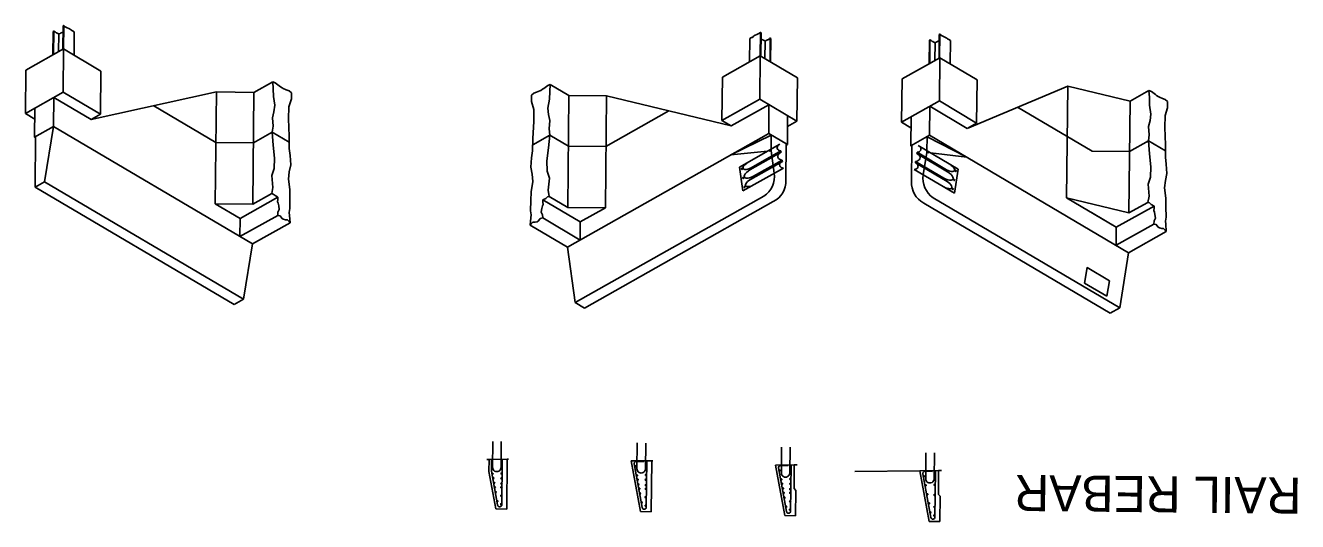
# Model space of a CAD drawing. Extents: x 631918 to 632319, y 373181 to 373282.
# Drawn here: x 631918.3 to 632006.4, y 373247.3 to 373281.7 of the extents above; entities that cross this region are included whole.
import ezdxf

# ---------------------------------------------------------------- set-up
doc = ezdxf.new("R2010")
doc.units = 0
for name, color, linetype in [('B_Boring', 7, 'Continuous'), ('BD-PROP-COSS', 7, 'Continuous'), ('BD-REMOVE', 7, 'Continuous'), ('R_Border_Scale', 7, 'Continuous'), ('R_Proposed Const Limits Cut', 7, 'Continuous'), ('R_Road Edge of Travel', 7, 'Continuous'), ('R_Shade Removal', 7, 'Continuous')]:
    doc.layers.add(name, color=color, linetype=linetype)

msp = doc.modelspace()

# ---------------------------------------------------------------- linework, layer by layer
at = {"layer": 'B_Boring'}
for p, q in [((631969.792, 373272.95), (631969.934, 373272.964)), ((631969.934, 373272.964), (631969.935, 373273.03)), ((631970.151, 373271.419), (631969.934, 373272.964)), ((631980.469, 373271.316), (631980.716, 373272.857)), ((631980.716, 373272.857), (631980.717, 373272.922)), ((631980.858, 373272.84), (631980.716, 373272.857))]:
    msp.add_line(p, q, dxfattribs=at)
at = {"layer": 'BD-PROP-COSS'}
for p, q in [((631950.664, 373252.836), (631950.646, 373251.044)), ((631951.247, 373252.83), (631951.229, 373251.038)), ((631960.663, 373252.736), (631960.645, 373250.945)), ((631961.247, 373252.73), (631961.229, 373250.939)), ((631970.661, 373252.454), (631970.643, 373250.663)), ((631971.244, 373252.449), (631971.226, 373250.657)), ((631980.657, 373252.052), (631980.64, 373250.261)), ((631981.241, 373252.047), (631981.223, 373250.255)), ((631950.56, 373250.791), (631950.568, 373251.599)), ((631951.287, 373248.474), (631951.318, 373251.591)), ((631960.452, 373251.286), (631960.996, 373248.267)), ((631961.121, 373251.452), (631960.597, 373251.457)), ((631961.286, 373248.292), (631961.318, 373251.492)), ((631971.119, 373251.171), (631970.595, 373251.176)), ((631971.283, 373248.01), (631971.315, 373251.21)), ((631950.56, 373250.791), (631950.982, 373248.447)), ((631970.45, 373251.004), (631970.994, 373247.985)), ((631980.447, 373250.602), (631980.991, 373247.583)), ((631981.115, 373250.768), (631980.592, 373250.774)), ((631981.28, 373247.608), (631981.312, 373250.808))]:
    msp.add_line(p, q, dxfattribs=at)
for centre in [(631950.606, 373251.211), (631951.274, 373251.329), (631960.528, 373251.112), (631961.273, 373251.23), (631950.641, 373250.586), (631950.693, 373250.293), (631951.263, 373250.288), (631951.267, 373250.621), (631960.64, 373250.486), (631960.693, 373250.194), (631961.263, 373250.188), (631961.266, 373250.522), (631970.525, 373250.831), (631970.638, 373250.205), (631971.264, 373250.24), (631971.271, 373250.948), (631980.522, 373250.429), (631981.267, 373250.546), (631950.753, 373249.96), (631950.806, 373249.667), (631950.865, 373249.333), (631951.257, 373249.663), (631951.26, 373249.913), (631960.753, 373249.86), (631960.805, 373249.568), (631961.257, 373249.563), (631961.259, 373249.813), (631970.69, 373249.912), (631970.75, 373249.578), (631971.257, 373249.532), (631971.261, 373249.907), (631980.634, 373249.802), (631981.26, 373249.838), (631950.978, 373248.707), (631951.246, 373248.496), (631951.251, 373249.08), (631960.865, 373249.234), (631960.977, 373248.608), (631961.251, 373248.98), (631970.803, 373249.286), (631970.863, 373248.952), (631971.249, 373248.698), (631971.254, 373249.282), (631980.747, 373249.176), (631980.859, 373248.55), (631981.253, 373249.13), (631961.245, 373248.397), (631970.975, 373248.326), (631971.243, 373248.115), (631980.972, 373247.924), (631981.239, 373247.713), (631981.245, 373248.296)]:
    msp.add_circle(centre, 0.0417, dxfattribs=at)
for centre, radius, start, end in [((631960.596, 373251.312), 0.146, 89.43036, 190.21458), ((631970.594, 373251.03), 0.146, 89.43036, 190.21458), ((631950.938, 373251.041), 0.292, 179.43036, 359.43036), ((631960.937, 373250.942), 0.292, 179.43036, 359.43036), ((631970.935, 373250.66), 0.292, 179.43036, 359.43036), ((631980.59, 373250.628), 0.146, 89.43036, 190.21458), ((631980.931, 373250.258), 0.292, 179.43036, 359.43036), ((631961.14, 373248.293), 0.146, 190.21458, 359.43036), ((631971.138, 373248.011), 0.146, 190.21458, 359.43036), ((631981.134, 373247.609), 0.146, 190.21458, 359.43036)]:
    msp.add_arc(centre, radius, start, end, dxfattribs=at)
msp.add_ellipse((631951.134, 373248.476), major_axis=(-0.002, -0.161), ratio=0.951273, start_param=4.900609, end_param=7.853982, dxfattribs=at)
at = {"layer": 'R_Border_Scale'}
for p, q in [((631931.485, 373273.544), (631927.18, 373276.087)), ((631992.156, 373272.941), (631986.99, 373275.992)), ((631958.498, 373273.275), (631962.853, 373275.732)), ((631934.083, 373273.518), (631935.39, 373274.255)), ((631936.563, 373273.562), (631935.39, 373274.255)), ((631953.422, 373273.395), (631954.608, 373274.064)), ((631955.9, 373273.301), (631954.608, 373274.064)), ((631931.485, 373273.544), (631934.083, 373273.518)), ((631958.498, 373273.275), (631955.9, 373273.301)), ((631994.754, 373272.915), (631996.061, 373273.652)), ((631997.234, 373272.959), (631996.061, 373273.652)), ((631992.156, 373272.941), (631994.754, 373272.915)), ((631950.403, 373251.591), (631951.664, 373251.604)), ((631960.246, 373251.49), (631961.663, 373251.504)), ((631970.244, 373251.209), (631971.536, 373251.222)), ((631980.24, 373250.806), (631981.532, 373250.819))]:
    msp.add_line(p, q, dxfattribs=at)
at = {"layer": 'R_Proposed Const Limits Cut'}
for p, q in [((631967.742, 373271.841), (631970.547, 373273.424)), ((631982.886, 373271.69), (631980.112, 373273.329)), ((631968.467, 373271.649), (631970.626, 373272.867)), ((631968.499, 373270.988), (631970.714, 373272.237)), ((631968.547, 373271.794), (631970.613, 373272.96)), ((631968.715, 373271.21), (631970.701, 373272.33)), ((631970.626, 373272.867), (631970.613, 373272.96)), ((631970.714, 373272.237), (631970.701, 373272.33)), ((631979.922, 373272.146), (631979.937, 373272.238)), ((631981.9, 373271.079), (631979.937, 373272.238)), ((631980.023, 373272.773), (631980.038, 373272.866)), ((631982.156, 373271.513), (631980.023, 373272.773)), ((631982.08, 373271.66), (631980.038, 373272.866)), ((631967.974, 373270.19), (631967.742, 373271.841)), ((631967.974, 373270.19), (631970.779, 373271.773)), ((631982.621, 373270.045), (631979.848, 373271.683)), ((631982.112, 373270.852), (631979.922, 373272.146)), ((631982.621, 373270.045), (631982.886, 373271.69)), ((631991.644, 373263.811), (631991.816, 373264.88)), ((631993.187, 373262.899), (631993.359, 373263.969))]:
    msp.add_line(p, q, dxfattribs=at)
for points in [[(631993.359, 373263.969), (631991.816, 373264.88), (631991.816, 373264.88), (631993.359, 373263.969)], [(631993.187, 373262.899), (631991.644, 373263.811), (631991.644, 373263.811), (631993.187, 373262.899)]]:
    msp.add_lwpolyline(points, close=True, dxfattribs=at)
for centre, major_axis, ratio, start_param, end_param in [((631970.616, 373273.188), (0.267, -0.005), 0.854896, 2.174054, 4.712811), ((631980.038, 373273.094), (0.267, -0.001), 0.854896, 4.711967, 7.250724), ((631970.705, 373272.594), (0.309, -0.005), 0.854896, 2.174054, 4.712811), ((631979.938, 373272.503), (0.309, -0.001), 0.854896, 4.711967, 7.250724), ((631968.44, 373271.984), (-0.44, -0.248), 0.432148, 4.712389, 7.853982), ((631968.591, 373271.43), (-0.508, -0.287), 0.432148, 4.712389, 7.853982), ((631970.783, 373272.002), (0.267, -0.005), 0.854896, 2.174054, 4.712811), ((631979.848, 373271.911), (0.267, -0.001), 0.854896, 4.711967, 7.250724), ((631982.028, 373271.296), (0.502, -0.297), 0.432148, 4.712389, 7.853982), ((631982.191, 373271.847), (0.435, -0.257), 0.432148, 4.712389, 7.853982), ((631968.606, 373270.798), (-0.44, -0.248), 0.432148, 4.712389, 7.853982), ((631982.001, 373270.664), (0.435, -0.257), 0.432148, 4.712389, 7.853982)]:
    msp.add_ellipse(centre, major_axis=major_axis, ratio=ratio, start_param=start_param, end_param=end_param, dxfattribs=at)
for centre, major_axis in [((631967.915, 373271.727), (-0.0216, -0.0437)), ((631968.539, 373271.74), (-0.0216, -0.0437)), ((631982.086, 373271.605), (0.0207, -0.0441)), ((631982.711, 373271.58), (0.0207, -0.0441)), ((631968.003, 373271.098), (-0.0216, -0.0437)), ((631968.091, 373270.468), (-0.0216, -0.0437)), ((631968.628, 373271.11), (-0.0216, -0.0437)), ((631981.985, 373270.978), (0.0207, -0.0441)), ((631982.61, 373270.952), (0.0207, -0.0441)), ((631982.509, 373270.325), (0.0207, -0.0441))]:
    msp.add_ellipse(centre, major_axis=major_axis, ratio=0.68171, dxfattribs=at)
at = {"layer": 'R_Road Edge of Travel'}
for p, q in [((631920.205, 373279.609), (631920.221, 373281.244)), ((631920.246, 373279.632), (631920.262, 373281.267)), ((631920.598, 373279.831), (631920.61, 373281.062)), ((631920.89, 373279.996), (631920.906, 373281.631)), ((631920.931, 373280.019), (631920.947, 373281.654)), ((631921.667, 373279.595), (631921.683, 373281.219)), ((631969.179, 373279.539), (631969.195, 373281.174)), ((631969.219, 373279.515), (631969.236, 373281.15)), ((631981.602, 373279.416), (631981.618, 373281.051)), ((631968.435, 373279.13), (631968.451, 373280.754)), ((631969.508, 373279.345), (631969.52, 373280.575)), ((631969.856, 373279.139), (631969.872, 373280.774)), ((631969.897, 373279.115), (631969.913, 373280.75)), ((631980.876, 373279.006), (631980.892, 373280.641)), ((631980.917, 373279.029), (631980.933, 373280.664)), ((631981.269, 373279.228), (631981.281, 373280.459)), ((631981.561, 373279.392), (631981.577, 373281.028)), ((631982.338, 373278.992), (631982.354, 373280.616))]:
    msp.add_line(p, q, dxfattribs=at)
for points in [[(631920.221, 373281.244), (631920.262, 373281.267), (631920.308, 373281.242), (631920.346, 373281.206), (631920.421, 373281.15), (631920.457, 373281.136), (631920.537, 373281.104), (631920.61, 373281.062), (631920.691, 373281.09), (631920.736, 373281.115), (631920.839, 373281.166), (631920.868, 373281.17), (631920.902, 373281.19)], [(631920.906, 373281.631), (631920.947, 373281.654), (631921.059, 373281.562), (631921.148, 373281.517), (631921.348, 373281.429), (631921.423, 373281.37), (631921.48, 373281.32), (631921.511, 373281.296), (631921.566, 373281.275), (631921.683, 373281.219)], [(631969.236, 373281.15), (631969.195, 373281.174), (631969.081, 373281.085), (631968.992, 373281.041), (631968.79, 373280.957), (631968.714, 373280.9), (631968.656, 373280.851), (631968.624, 373280.828), (631968.569, 373280.808), (631968.451, 373280.754)], [(631981.577, 373281.028), (631981.618, 373281.051), (631981.73, 373280.959), (631981.819, 373280.914), (631982.019, 373280.825), (631982.094, 373280.767), (631982.151, 373280.717), (631982.182, 373280.693), (631982.237, 373280.672), (631982.354, 373280.616)], [(631969.913, 373280.75), (631969.872, 373280.774), (631969.827, 373280.749), (631969.787, 373280.714), (631969.711, 373280.659), (631969.675, 373280.646), (631969.594, 373280.616), (631969.52, 373280.575), (631969.44, 373280.605), (631969.396, 373280.631), (631969.293, 373280.685), (631969.265, 373280.689), (631969.231, 373280.709)], [(631980.892, 373280.641), (631980.933, 373280.664), (631980.978, 373280.638), (631981.017, 373280.602), (631981.092, 373280.546), (631981.128, 373280.533), (631981.208, 373280.5), (631981.281, 373280.459), (631981.362, 373280.487), (631981.407, 373280.512), (631981.51, 373280.563), (631981.539, 373280.567), (631981.573, 373280.586)]]:
    msp.add_lwpolyline(points, dxfattribs=at)
at = {"layer": 'R_Shade Removal'}
for p, q in [((631918.328, 373278.55), (631920.941, 373280.024)), ((631920.911, 373277.024), (631920.941, 373280.024)), ((631923.524, 373278.498), (631920.941, 373280.024)), ((631966.557, 373278.071), (631969.169, 373279.545)), ((631969.14, 373276.545), (631969.169, 373279.545)), ((631971.753, 373278.019), (631969.169, 373279.545)), ((631978.999, 373277.947), (631981.612, 373279.421)), ((631981.582, 373276.421), (631981.612, 373279.421)), ((631984.195, 373277.895), (631981.612, 373279.421)), ((631918.298, 373275.55), (631918.328, 373278.55)), ((631923.494, 373275.499), (631923.524, 373278.498)), ((631934.118, 373277.018), (631935.425, 373277.755)), ((631955.935, 373276.801), (631954.643, 373277.564)), ((631966.527, 373275.071), (631966.557, 373278.071)), ((631971.723, 373275.019), (631971.753, 373278.019)), ((631978.969, 373274.947), (631978.999, 373277.947)), ((631984.165, 373274.895), (631984.195, 373277.895)), ((631918.298, 373275.55), (631920.911, 373277.024)), ((631920.238, 373274.656), (631920.258, 373276.656)), ((631922.841, 373275.13), (631920.258, 373276.656)), ((631923.494, 373275.499), (631920.911, 373277.024)), ((631931.52, 373277.044), (631922.841, 373275.13)), ((631931.52, 373277.044), (631931.443, 373269.294)), ((631931.52, 373277.044), (631934.118, 373277.018)), ((631934.118, 373277.018), (631934.041, 373269.268)), ((631955.935, 373276.801), (631955.858, 373269.052)), ((631958.533, 373276.775), (631955.935, 373276.801)), ((631958.533, 373276.775), (631958.456, 373269.026)), ((631958.533, 373276.775), (631967.173, 373274.689)), ((631990.469, 373277.458), (631983.511, 373274.527)), ((631990.469, 373277.458), (631990.392, 373269.708)), ((631990.469, 373277.458), (631994.789, 373276.415)), ((631994.789, 373276.415), (631996.096, 373277.152)), ((631918.931, 373273.919), (631918.951, 373275.919)), ((631966.527, 373275.071), (631969.14, 373276.545)), ((631967.173, 373274.689), (631969.785, 373276.163)), ((631971.723, 373275.019), (631969.14, 373276.545)), ((631969.766, 373274.164), (631969.785, 373276.163)), ((631978.969, 373274.947), (631981.582, 373276.421)), ((631980.909, 373274.053), (631980.928, 373276.053)), ((631983.511, 373274.527), (631980.928, 373276.053)), ((631984.165, 373274.895), (631981.582, 373276.421)), ((631994.789, 373276.415), (631994.712, 373268.665)), ((631918.944, 373275.169), (631918.298, 373275.55)), ((631922.841, 373275.13), (631923.494, 373275.499)), ((631967.173, 373274.689), (631966.527, 373275.071)), ((631971.057, 373273.401), (631971.077, 373275.401)), ((631971.069, 373274.651), (631971.723, 373275.019)), ((631979.615, 373274.566), (631978.969, 373274.947)), ((631979.602, 373273.316), (631979.622, 373275.316)), ((631983.511, 373274.527), (631984.165, 373274.895)), ((631918.931, 373273.919), (631920.238, 373274.656)), ((631919.622, 373270.829), (631920.238, 373274.656)), ((631934.014, 373266.519), (631920.238, 373274.656)), ((631955.83, 373266.302), (631969.766, 373274.164)), ((631967.153, 373272.689), (631969.945, 373274.058)), ((631971.057, 373273.401), (631969.766, 373274.164)), ((631969.935, 373273.078), (631969.945, 373274.058)), ((631979.602, 373273.316), (631980.909, 373274.053)), ((631994.685, 373265.915), (631980.909, 373274.053)), ((631919.003, 373273.876), (631918.931, 373273.919)), ((631918.969, 373270.46), (631919.004, 373273.96)), ((631970.96, 373270.943), (631970.985, 373273.443)), ((631970.984, 373273.36), (631971.057, 373273.401)), ((631979.674, 373273.273), (631979.602, 373273.316)), ((631979.65, 373270.857), (631979.675, 373273.357)), ((631980.717, 373272.971), (631980.727, 373273.95)), ((631983.492, 373272.527), (631980.727, 373273.95)), ((631967.153, 373272.689), (631969.69, 373272.94)), ((631983.492, 373272.527), (631980.96, 373272.828)), ((631918.969, 373270.46), (631919.622, 373270.829)), ((631933.398, 373262.691), (631919.622, 373270.829)), ((631932.745, 373262.323), (631918.969, 373270.46)), ((631933.165, 373268.277), (631935.778, 373269.751)), ((631934.041, 373269.268), (631935.348, 373270.005)), ((631955.858, 373269.052), (631954.566, 373269.814)), ((631956.369, 373262.463), (631969.434, 373269.833)), ((631994.069, 373262.088), (631981.154, 373269.717)), ((631990.392, 373269.708), (631994.712, 373268.665)), ((631993.836, 373267.674), (631990.392, 373269.708)), ((631933.165, 373268.277), (631931.443, 373269.294)), ((631931.443, 373269.294), (631934.041, 373269.268)), ((631956.714, 373268.043), (631954.131, 373269.569)), ((631958.456, 373269.026), (631955.858, 373269.052)), ((631956.714, 373268.043), (631958.456, 373269.026)), ((631957.015, 373262.081), (631970.08, 373269.452)), ((631993.416, 373261.719), (631980.501, 373269.348)), ((631993.836, 373267.674), (631996.449, 373269.148)), ((631994.712, 373268.665), (631996.019, 373269.402)), ((631933.153, 373267.027), (631935.766, 373268.501)), ((631933.165, 373268.277), (631933.153, 373267.027)), ((631934.014, 373266.519), (631936.627, 373267.993)), ((631956.701, 373266.793), (631954.118, 373268.319)), ((631956.714, 373268.043), (631956.701, 373266.793)), ((631993.836, 373267.674), (631992.114, 373268.691)), ((631993.824, 373266.424), (631996.437, 373267.898)), ((631955.83, 373266.302), (631953.247, 373267.827)), ((631993.836, 373267.674), (631993.824, 373266.424)), ((631994.685, 373265.915), (631997.298, 373267.389)), ((631933.398, 373262.691), (631934.014, 373266.519)), ((631956.369, 373262.463), (631955.83, 373266.302)), ((631994.069, 373262.088), (631994.685, 373265.915)), ((631932.745, 373262.323), (631933.398, 373262.691)), ((631957.015, 373262.081), (631956.369, 373262.463)), ((631993.416, 373261.719), (631994.069, 373262.088)), ((631950.247, 373251.59), (631950.403, 373251.591)), ((631950.395, 373250.768), (631950.403, 373251.591)), ((631951.629, 373248.159), (631951.664, 373251.604)), ((631951.664, 373251.604), (631951.747, 373251.605)), ((631960.246, 373251.49), (631960.878, 373247.984)), ((631961.628, 373247.976), (631961.663, 373251.504)), ((631961.663, 373251.504), (631961.746, 373251.505)), ((631970.244, 373251.209), (631970.876, 373247.702)), ((631971.519, 373249.571), (631971.536, 373251.222)), ((631971.536, 373251.222), (631971.744, 373251.224)), ((631950.395, 373250.768), (631950.864, 373248.167)), ((631975.739, 373250.761), (631980.24, 373250.806)), ((631980.24, 373250.806), (631980.872, 373247.3)), ((631981.516, 373249.169), (631981.532, 373250.819)), ((631981.532, 373250.819), (631981.74, 373250.821)), ((631971.643, 373249.445), (631971.519, 373249.571)), ((631971.626, 373247.695), (631971.643, 373249.445)), ((631981.64, 373249.042), (631981.516, 373249.169)), ((631981.622, 373247.293), (631981.64, 373249.042)), ((631950.864, 373248.167), (631951.629, 373248.159)), ((631960.878, 373247.984), (631961.628, 373247.976)), ((631970.876, 373247.702), (631971.626, 373247.695)), ((631980.872, 373247.3), (631981.622, 373247.293))]:
    msp.add_line(p, q, dxfattribs=at)
for points in [[(631936.627, 373267.993), (631936.442, 373268.192), (631936.306, 373268.194), (631936.146, 373268.235), (631936.051, 373268.3), (631936.051, 373268.3), (631935.933, 373268.461), (631935.933, 373268.461), (631935.766, 373268.501), (631935.784, 373268.716), (631935.873, 373268.91), (631935.873, 373268.91), (631935.836, 373269.166), (631935.806, 373269.334), (631935.759, 373269.431), (631935.784, 373269.598), (631935.778, 373269.751), (631935.579, 373269.864), (631935.46, 373269.962), (631935.46, 373269.962), (631935.348, 373270.005), (631935.438, 373270.433), (631935.362, 373271.26), (631935.529, 373271.74), (631935.55, 373272.468), (631935.461, 373273.364), (631935.39, 373274.255), (631935.447, 373274.68), (631935.4, 373275.255), (631935.498, 373275.674), (631935.558, 373276.121), (631935.467, 373276.738), (631935.459, 373277.27), (631935.425, 373277.755)], [(631936.716, 373276.992), (631936.55, 373277.125), (631936.363, 373277.203), (631936.147, 373277.297), (631936.066, 373277.333), (631935.953, 373277.41), (631935.875, 373277.471), (631935.778, 373277.548), (631935.592, 373277.683), (631935.425, 373277.755)], [(631953.247, 373267.827), (631953.436, 373268.023), (631953.572, 373268.022), (631953.732, 373268.06), (631953.829, 373268.123), (631953.829, 373268.123), (631953.95, 373268.282), (631953.95, 373268.282), (631954.118, 373268.319), (631954.105, 373268.534), (631954.019, 373268.729), (631954.019, 373268.729), (631954.061, 373268.985), (631954.095, 373269.152), (631954.144, 373269.248), (631954.121, 373269.416), (631954.131, 373269.569), (631954.332, 373269.678), (631954.453, 373269.773), (631954.453, 373269.773), (631954.566, 373269.814), (631954.484, 373270.244), (631954.576, 373271.069), (631954.419, 373271.552), (631954.413, 373272.28), (631954.519, 373273.175), (631954.608, 373274.064), (631954.559, 373274.49), (631954.618, 373275.064), (631954.528, 373275.484), (631954.477, 373275.933), (631954.581, 373276.548), (631954.599, 373277.079), (631954.643, 373277.564)], [(631953.337, 373276.827), (631953.506, 373276.956), (631953.694, 373277.03), (631953.912, 373277.121), (631953.994, 373277.155), (631954.108, 373277.23), (631954.188, 373277.289), (631954.286, 373277.364), (631954.475, 373277.495), (631954.643, 373277.564)], [(631936.716, 373276.992), (631936.71, 373276.559), (631936.542, 373276.009), (631936.52, 373275.178), (631936.561, 373273.986), (631936.565, 373273.138), (631936.62, 373272.649), (631936.666, 373271.992), (631936.568, 373271.514), (631936.507, 373271.003), (631936.598, 373270.298), (631936.604, 373269.69), (631936.611, 373268.97), (631936.566, 373268.699), (631936.566, 373268.699), (631936.589, 373268.491), (631936.627, 373267.993)], [(631953.337, 373276.827), (631953.335, 373276.393), (631953.491, 373275.841), (631953.497, 373275.009), (631953.432, 373273.819), (631953.411, 373272.971), (631953.347, 373272.483), (631953.287, 373271.827), (631953.376, 373271.347), (631953.427, 373270.835), (631953.322, 373270.132), (631953.304, 373269.524), (631953.282, 373268.805), (631953.322, 373268.532), (631953.322, 373268.532), (631953.295, 373268.325), (631953.247, 373267.827)], [(631997.298, 373267.389), (631997.113, 373267.589), (631996.977, 373267.59), (631996.817, 373267.632), (631996.722, 373267.697), (631996.722, 373267.697), (631996.604, 373267.858), (631996.604, 373267.858), (631996.437, 373267.898), (631996.454, 373268.113), (631996.544, 373268.306), (631996.544, 373268.306), (631996.507, 373268.563), (631996.477, 373268.731), (631996.43, 373268.828), (631996.455, 373268.995), (631996.449, 373269.148), (631996.25, 373269.261), (631996.131, 373269.358), (631996.131, 373269.358), (631996.019, 373269.402), (631996.109, 373269.83), (631996.033, 373270.657), (631996.2, 373271.137), (631996.221, 373271.865), (631996.132, 373272.761), (631996.061, 373273.652), (631996.118, 373274.077), (631996.071, 373274.652), (631996.169, 373275.07), (631996.229, 373275.518), (631996.138, 373276.134), (631996.13, 373276.666), (631996.096, 373277.152)], [(631997.387, 373276.389), (631997.221, 373276.522), (631997.034, 373276.599), (631996.818, 373276.694), (631996.737, 373276.73), (631996.624, 373276.807), (631996.545, 373276.868), (631996.448, 373276.945), (631996.262, 373277.08), (631996.096, 373277.152)], [(631997.387, 373276.389), (631997.381, 373275.955), (631997.213, 373275.406), (631997.191, 373274.575), (631997.232, 373273.383), (631997.236, 373272.535), (631997.291, 373272.046), (631997.337, 373271.389), (631997.239, 373270.911), (631997.178, 373270.4), (631997.268, 373269.695), (631997.275, 373269.087), (631997.282, 373268.367), (631997.237, 373268.096), (631997.237, 373268.096), (631997.259, 373267.887), (631997.298, 373267.389)]]:
    msp.add_lwpolyline(points, dxfattribs=at)
for centre, radius, start, end in [((631968.54, 373271.193), 1.627, 303.33523, 7.98399), ((631969.342, 373270.894), 1.62, 297.10598, 1.75474), ((631981.267, 373270.775), 1.62, 177.10598, 241.75474), ((631982.075, 373271.058), 1.627, 170.87673, 235.52548)]:
    msp.add_arc(centre, radius, start, end, dxfattribs=at)

# ---------------------------------------------------------------- texts
at = {"layer": 'BD-REMOVE'}
msp.add_text('RAIL REBAR', height=2.5, rotation=179.43036, dxfattribs=at).set_placement((632006.661, 373250.332))

doc.saveas('drawing.dxf')
